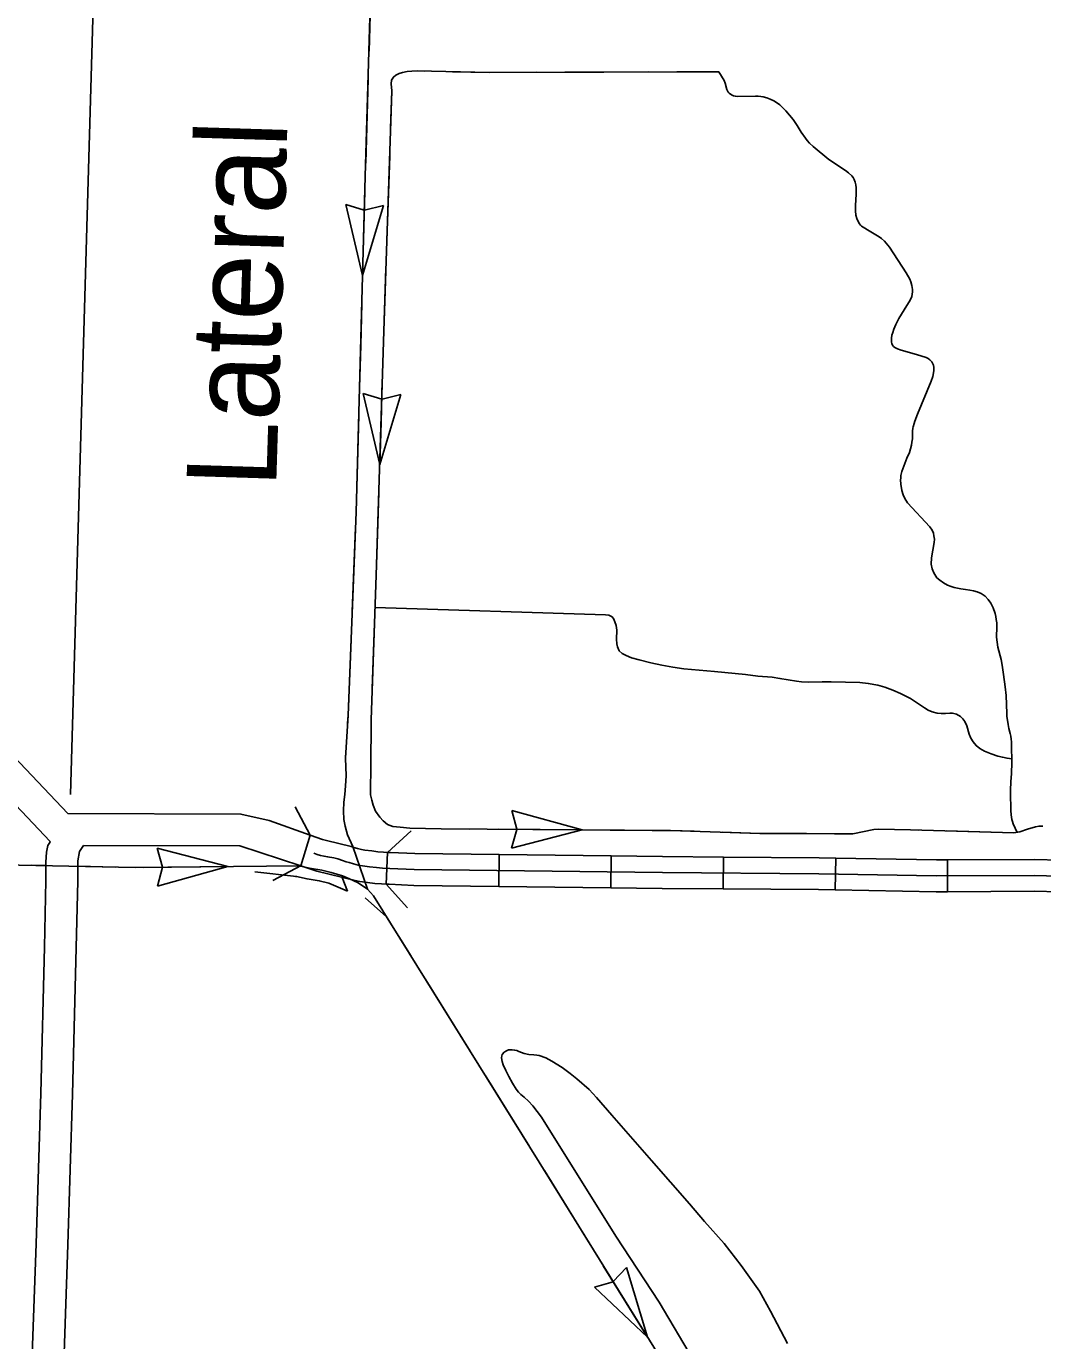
# Model space of a CAD drawing. Extents: x 1196286 to 1268366, y 2040822 to 2082115.
# Drawn here: x 1218140 to 1219934, y 2061099 to 2063420 of the extents above; entities that cross this region are included whole.
import ezdxf

# ---------------------------------------------------------------- set-up
doc = ezdxf.new("R2010")
doc.units = 0
for name, color, linetype in [('60', 7, 'Continuous'), ('61', 7, 'Continuous'), ('62', 7, 'Continuous'), ('63', 7, 'Continuous'), ('Level 72', 7, 'Continuous'), ('Level 83', 7, 'Continuous')]:
    doc.layers.add(name, color=color, linetype=linetype)

msp = doc.modelspace()

# ---------------------------------------------------------------- linework, layer by layer
at = {"layer": '60'}
msp.add_lwpolyline([(1218272.3, 2063944.2), (1218218.5, 2062063.5)], dxfattribs=at)
at = {"layer": '61'}
for p, q in [((1218777.8, 2061961.3), (1218775.3, 2061905.1)), ((1218974.8, 2061957.4), (1218974.2, 2061901.2)), ((1219172.8, 2061955), (1219172.1, 2061898.8)), ((1219370.7, 2061953), (1219370.2, 2061896.8)), ((1219569, 2061951.1), (1219567.9, 2061894.9)), ((1219766.3, 2061948), (1219766.6, 2061891.7))]:
    msp.add_line(p, q, dxfattribs=at)
for points in [[(1218775.3, 2061905.1), (1218767.4, 2061905.5), (1218755.5, 2061906.4), (1218742.6, 2061907.9), (1218729.1, 2061909.9), (1218720.6, 2061911.4), (1218653.1, 2061928.2), (1218644.2, 2061930.8), (1218625, 2061937.2), (1218641.6, 2061991.8)], [(1218777.8, 2061961.3), (1218770.7, 2061961.6), (1218761, 2061962.4), (1218749.9, 2061963.7), (1218738, 2061965.4), (1218731.8, 2061966.5), (1218724.8, 2061968.1), (1218718.4, 2061970), (1218713.9, 2061971.4), (1218670.3, 2061982.2), (1218663.2, 2061983.9), (1218641.4, 2061991.8)], [(1220136.9, 2061914.8), (1219919.4, 2061920.7), (1219746.6, 2061919.8), (1219539.2, 2061923.5), (1219263.2, 2061925.8), (1218825.1, 2061931.2), (1218781.8, 2061933), (1218769.1, 2061933.6), (1218758.3, 2061934.4), (1218746.2, 2061935.8), (1218733.5, 2061937.6), (1218726.2, 2061938.9), (1218717.7, 2061940.9), (1218710.2, 2061943.1), (1218704.9, 2061944.7), (1218698.2, 2061947.1), (1218690.1, 2061949.7), (1218682.9, 2061951.5), (1218672.2, 2061953.6), (1218665.9, 2061954.5), (1218659.6, 2061955.6), (1218653.7, 2061957.3), (1218648.1, 2061959.7)], [(1218974.8, 2061957.4), (1218825.8, 2061959.3), (1218783, 2061961.1), (1218777.8, 2061961.3)], [(1219172.8, 2061955), (1218974.8, 2061957.4)], [(1219370.7, 2061953), (1219263.5, 2061953.9), (1219172.8, 2061955)], [(1219569, 2061951.1), (1219539.6, 2061951.7), (1219370.7, 2061953)], [(1219766.3, 2061948), (1219746.8, 2061947.9), (1219569, 2061951.1)], [(1219965.2, 2061947.6), (1219919.7, 2061948.8), (1219766.3, 2061948)], [(1218974.2, 2061901.2), (1218824.3, 2061903), (1218780.6, 2061904.9), (1218775.3, 2061905.1)], [(1219172.1, 2061898.8), (1218974.2, 2061901.2)], [(1219370.2, 2061896.8), (1219262.9, 2061897.7), (1219172.1, 2061898.8)], [(1219567.9, 2061894.9), (1219538.9, 2061895.4), (1219370.2, 2061896.8)], [(1219766.6, 2061891.7), (1219746.4, 2061891.6), (1219567.9, 2061894.9)], [(1219963.7, 2061891.3), (1219919.1, 2061892.5), (1219766.6, 2061891.7)]]:
    msp.add_lwpolyline(points, dxfattribs=at)
at = {"layer": '62'}
for points in [[(1219362.9, 2063339.5), (1219372.3, 2063324), (1219374.1, 2063319.2), (1219376.6, 2063308.2), (1219377.7, 2063306), (1219379, 2063303.4), (1219380.8, 2063301.6), (1219383, 2063299.9), (1219386, 2063298.3), (1219388.8, 2063297.1), (1219391.9, 2063296.3), (1219395.6, 2063295.7), (1219427.6, 2063296.7), (1219432.3, 2063296.4), (1219437, 2063295.8), (1219441, 2063295.1), (1219447.3, 2063293.3), (1219453.3, 2063291), (1219459.7, 2063288.1), (1219464.3, 2063285.5), (1219470.5, 2063281.3), (1219480.9, 2063270.8), (1219493.8, 2063255.4), (1219501.2, 2063244.5), (1219508.3, 2063232.9), (1219515.4, 2063222.1), (1219518.4, 2063218.2), (1219522.5, 2063213.4), (1219529.3, 2063207.5), (1219557.1, 2063184.7), (1219565.2, 2063179.1), (1219576.5, 2063171.9), (1219586.5, 2063165.4), (1219591.7, 2063161.3), (1219597.3, 2063155.9), (1219599.7, 2063152.7), (1219601.6, 2063149.1), (1219603.3, 2063144.4), (1219604.4, 2063139.6), (1219605, 2063134.7), (1219605, 2063123.6), (1219604.1, 2063103.4), (1219604.2, 2063093.8), (1219604.8, 2063086.1), (1219606, 2063080.6), (1219608.4, 2063074.9), (1219610.8, 2063071.1), (1219612.8, 2063068.8), (1219614.8, 2063067.1), (1219630.9, 2063057.1), (1219645.5, 2063048.3), (1219649.7, 2063045.1), (1219655.4, 2063040.3), (1219663.8, 2063029.9), (1219693.1, 2062984.4), (1219699.7, 2062973.2), (1219701.6, 2062968.4), (1219703.4, 2062961.9), (1219704.5, 2062955.3), (1219704.6, 2062951.2), (1219704.2, 2062946.8), (1219703.2, 2062942.8), (1219700.6, 2062936.4), (1219689.9, 2062919.1), (1219680.6, 2062903.7), (1219675.3, 2062893.2), (1219671.6, 2062885.2), (1219669.6, 2062879.4), (1219668.2, 2062874.2), (1219667.4, 2062869.3), (1219667.3, 2062865.6), (1219667.3, 2062862.3), (1219667.9, 2062859.5), (1219669.2, 2062856.8), (1219671.1, 2062854.7), (1219673.5, 2062852.7), (1219678.3, 2062850.4), (1219684.7, 2062848.1), (1219707.3, 2062841.3), (1219719.4, 2062838), (1219728.9, 2062835.1), (1219732.3, 2062833.3), (1219735, 2062831), (1219738.4, 2062827.3), (1219740.2, 2062824.1), (1219741.5, 2062821.2), (1219742.1, 2062817.6), (1219742.2, 2062812.3), (1219741.7, 2062808), (1219740.3, 2062801.3), (1219737.6, 2062793.3), (1219713.5, 2062734.8), (1219708.8, 2062722.7), (1219707.2, 2062718.2), (1219705.9, 2062712.8), (1219705.3, 2062710.3), (1219704.8, 2062704.8)], [(1219704.8, 2062704.8), (1219704.7, 2062697.8), (1219704.4, 2062691.4), (1219703.6, 2062685.7), (1219702.7, 2062680.2), (1219701.2, 2062673.9), (1219699, 2062667.4), (1219694.7, 2062657.2), (1219689.1, 2062643.4), (1219685.8, 2062633.8), (1219684.1, 2062626.8), (1219683.7, 2062622.1), (1219683.4, 2062619.1), (1219683.7, 2062611.3), (1219685.6, 2062600.2), (1219688, 2062592.3), (1219690.8, 2062586), (1219695.5, 2062578.2), (1219735.4, 2062536.1), (1219739.4, 2062529.9), (1219741.4, 2062524.9), (1219742.4, 2062520), (1219743.3, 2062514.1), (1219742.8, 2062508.3), (1219738.1, 2062481.2), (1219737.7, 2062470), (1219739, 2062462.1), (1219741.9, 2062454.7), (1219747.3, 2062446), (1219752.6, 2062441.8), (1219759.1, 2062437.2), (1219766.1, 2062433.1), (1219772.5, 2062430.7), (1219778, 2062429.2), (1219790, 2062426.3), (1219798, 2062425.1), (1219805.5, 2062424.5), (1219812.3, 2062423.3), (1219818.8, 2062421.2), (1219826, 2062418.2), (1219832.8, 2062413.6), (1219837.9, 2062408), (1219842.8, 2062401), (1219847, 2062393.3), (1219850.6, 2062382.9), (1219851.9, 2062377.8), (1219852.5, 2062372.2), (1219853.3, 2062366.4), (1219853.6, 2062359.4), (1219853.1, 2062341.3), (1219853.7, 2062332.3), (1219855.3, 2062323.4), (1219860.9, 2062301.6), (1219862.6, 2062291.7), (1219865.4, 2062275.6), (1219868.3, 2062253.8), (1219869.8, 2062238.3), (1219871.1, 2062206.6), (1219871.3, 2062201.3), (1219872.1, 2062194.5), (1219873.5, 2062187.1), (1219874.8, 2062180.1), (1219877.1, 2062171.3), (1219878.2, 2062166.2), (1219878.7, 2062161.3), (1219879.1, 2062156.2), (1219879.2, 2062150.7), (1219879.8, 2062120), (1219879.2, 2062100.4), (1219878.3, 2062085.8), (1219877.7, 2062071.3), (1219877.6, 2062058.3), (1219878.1, 2062043.9), (1219878.3, 2062035.1), (1219878.7, 2062027.6), (1219879.7, 2062019.2), (1219880.8, 2062015.5), (1219882.1, 2062011.8), (1219889.3, 2061996.3)], [(1218756.1, 2062393.4), (1219162.9, 2062380.6), (1219168.7, 2062380.1), (1219174.2, 2062377.3), (1219177.2, 2062372.9), (1219181.6, 2062361.8), (1219182.5, 2062353.4), (1219181.9, 2062337.7), (1219182.6, 2062329.3), (1219183.9, 2062323.9), (1219186.9, 2062317.3), (1219192, 2062312.2), (1219199.3, 2062308.7), (1219208.5, 2062304.9), (1219221.8, 2062301.1), (1219242.8, 2062295.9), (1219262.3, 2062291.9), (1219281.6, 2062288.1), (1219301.2, 2062285.2), (1219341.4, 2062281.9), (1219355.1, 2062280.7), (1219409.7, 2062275.1), (1219431.8, 2062272.1), (1219456.8, 2062270.4), (1219470.5, 2062268.5), (1219500, 2062263.4), (1219508.9, 2062262.2), (1219520.5, 2062261.8), (1219545.3, 2062262.4), (1219560.7, 2062262.2), (1219611.5, 2062260.9), (1219626.5, 2062259.6), (1219643.3, 2062256.5), (1219655.6, 2062252.8), (1219670.1, 2062247.4), (1219683.2, 2062241.8), (1219701.1, 2062233), (1219725.8, 2062216.5), (1219732.2, 2062212.6), (1219739.5, 2062209.4), (1219748, 2062207), (1219755.2, 2062206.5), (1219763, 2062206.4), (1219770.5, 2062207), (1219775.2, 2062206.8), (1219782.2, 2062205.2), (1219789.5, 2062201), (1219793.3, 2062197.2), (1219796.7, 2062192.5), (1219800.2, 2062184.5), (1219804.5, 2062169.9), (1219807.7, 2062163), (1219811.4, 2062156.3), (1219816.7, 2062149.8), (1219823.1, 2062144.4), (1219831.6, 2062139.7), (1219843.2, 2062135.3), (1219855.4, 2062131.2), (1219863.2, 2062129.2), (1219871.6, 2062127.5), (1219879.7, 2062126.4)], [(1219483.9, 2061093.8), (1219454.1, 2061151.4), (1219434.2, 2061186.3), (1219402.1, 2061231.8), (1219372.3, 2061270.4), (1219337.4, 2061309.7), (1219311, 2061340.7), (1219243.8, 2061417.1), (1219174.1, 2061497.4), (1219146.5, 2061528.4), (1219133.7, 2061542.8), (1219112.2, 2061561.4), (1219100.4, 2061570.7), (1219086.2, 2061581.4), (1219067.8, 2061592.7), (1219057.1, 2061598.2), (1219045.5, 2061602.5), (1219041.4, 2061603.3), (1219036.1, 2061603.5), (1219027.6, 2061604.1), (1219019.2, 2061606.1), (1219009.7, 2061609.9), (1219006, 2061611.3), (1219002.1, 2061612.2), (1218997.9, 2061612.8), (1218991.4, 2061612.3), (1218988.1, 2061611), (1218984, 2061608.6), (1218980.2, 2061604.2), (1218979.4, 2061602), (1218979.1, 2061598.4), (1218980.2, 2061592.1), (1218982.3, 2061586.3), (1218986.8, 2061576.2), (1218992.2, 2061565.3), (1218998.3, 2061553.8), (1219004.9, 2061543), (1219008.8, 2061538.1), (1219013.2, 2061533.7), (1219019.1, 2061528.8), (1219027, 2061521.8), (1219034.2, 2061513.9), (1219049.7, 2061493.5), (1219180.9, 2061283.7), (1219257.6, 2061167.1), (1219378.4, 2060962.2)]]:
    msp.add_lwpolyline(points, dxfattribs=at)
at = {"layer": '63'}
for p, q in [((1218734, 2062980), (1218704.1, 2063105.2)), ((1218704.1, 2063105.2), (1218736.9, 2063095.4)), ((1218734, 2062980), (1218770.7, 2063103.4)), ((1218770.7, 2063103.4), (1218737.4, 2063095.4)), ((1218764.1, 2062646.3), (1218735, 2062771.6)), ((1218735, 2062771.6), (1218767.8, 2062761.7)), ((1218764.1, 2062646.3), (1218801.6, 2062769.4)), ((1218801.6, 2062769.4), (1218768.2, 2062761.7)), ((1219121.4, 2062000.9), (1218997.3, 2062035.1)), ((1218997.3, 2062035.1), (1219005.9, 2062002)), ((1218996.8, 2061968.5), (1219005.9, 2062001.5)), ((1219121.4, 2062000.9), (1218996.8, 2061968.5)), ((1218495.9, 2061936.2), (1218371.3, 2061968.4)), ((1218371.3, 2061968.4), (1218380.5, 2061935.4)), ((1218495.9, 2061936.2), (1218371.9, 2061901.7)), ((1218371.9, 2061901.7), (1218380.5, 2061934.9)), ((1218707.1, 2061892.5), (1218698, 2061917)), ((1219199.8, 2061228.3), (1219176.4, 2061203.4)), ((1219236.9, 2061105.1), (1219199.8, 2061228.3)), ((1219143.2, 2061193.3), (1219176, 2061203.1)), ((1219236.9, 2061105.1), (1219143.2, 2061193.3))]:
    msp.add_line(p, q, dxfattribs=at)
for points in [[(1218756.3, 2063757.3), (1218738.7, 2063154.7), (1218722.6, 2062561.9), (1218708.3, 2062203.4), (1218703.7, 2062127.3), (1218704.6, 2062096.3), (1218703.8, 2062078.6), (1218702.7, 2062063.7), (1218701, 2062049.9), (1218700.3, 2062034.5), (1218700.8, 2062019.4), (1218703, 2062007.3), (1218707.3, 2061992.1), (1218716.4, 2061971.8), (1218723.3, 2061952.7), (1218742.7, 2061896.2)], [(1218749.5, 2063524.3), (1218745.2, 2063375.9)], [(1219362.9, 2063339.5), (1218957.4, 2063338.4), (1218830, 2063340.9), (1218821, 2063340.6), (1218812.7, 2063339.8), (1218804.5, 2063338.5), (1218798.5, 2063336.6), (1218792.5, 2063333.7), (1218788.2, 2063330), (1218785, 2063324.8), (1218784.3, 2063318.3), (1218785.6, 2063305.8), (1218771.4, 2062881.7), (1218758.1, 2062450.7), (1218749.1, 2062195)], [(1218843.1, 2063340.6), (1218830, 2063340.9), (1218821, 2063340.6), (1218812.7, 2063339.8), (1218804.5, 2063338.5), (1218798.5, 2063336.6), (1218792.5, 2063333.7), (1218788.2, 2063330), (1218785, 2063324.8), (1218784.3, 2063318.3), (1218785.6, 2063305.8), (1218783.4, 2063240)], [(1219041.1, 2063338.7), (1218957.4, 2063338.4), (1218892.6, 2063339.7)], [(1219239.1, 2063339.2), (1219090.6, 2063338.8)], [(1219362.9, 2063339.5), (1219288.6, 2063339.3)], [(1218743.8, 2063326.4), (1218739.4, 2063178)], [(1218781.7, 2063190.5), (1218776.8, 2063042.1)], [(1218738, 2063128.5), (1218734, 2062980)], [(1218775.1, 2062992.6), (1218771.4, 2062881.7), (1218770.3, 2062844.2)], [(1218732.7, 2062930.6), (1218730.6, 2062856.3)], [(1218730.6, 2062856.3), (1218728.6, 2062782.1)], [(1218768.7, 2062794.7), (1218766.4, 2062720.5)], [(1218727.3, 2062732.6), (1218723.2, 2062584.2)], [(1218766.4, 2062720.5), (1218764.1, 2062646.3)], [(1218762.6, 2062596.8), (1218758.1, 2062450.7), (1218758, 2062448.4)], [(1218721.5, 2062534.7), (1218715.6, 2062386.3)], [(1218756.3, 2062398.9), (1218751, 2062250.5)], [(1218713.6, 2062336.9), (1218708.3, 2062203.4), (1218707.4, 2062188.5)], [(1218749.3, 2062201), (1218749.1, 2062195), (1218748.5, 2062109.8), (1218747.6, 2062072.4), (1218748.1, 2062062.8), (1218749.9, 2062053.6), (1218750.1, 2062052.8)], [(1218749.1, 2062195), (1218748.5, 2062109.8), (1218747.6, 2062072.4), (1218748.1, 2062062.8), (1218749.9, 2062053.6), (1218752.8, 2062044.6), (1218756.9, 2062034.1), (1218764.1, 2062023.4), (1218769.9, 2062017.1), (1218777.8, 2062010.7), (1218787.1, 2062006.9), (1218800.1, 2062005.5), (1218817.4, 2062003.8), (1218872.4, 2062002.7), (1219277.5, 2061999.8), (1219435.1, 2061994.6), (1219599.5, 2061994.1), (1219636.4, 2062001.4), (1219644.6, 2062002.5), (1219701, 2062000.8), (1219883.4, 2061995.9), (1219893.8, 2061997.4), (1219907.8, 2062002), (1219921.4, 2062006.2), (1219928.1, 2062007.8), (1219934.7, 2062007.5)], [(1218704.4, 2062139.1), (1218703.7, 2062127.3), (1218704.6, 2062096.3), (1218703.8, 2062078.6), (1218702.7, 2062063.7), (1218701, 2062049.9), (1218700.3, 2062034.5), (1218700.8, 2062019.4), (1218703, 2062007.3), (1218707.3, 2061992.1), (1218707.5, 2061991.7)], [(1218776.3, 2062012), (1218777.8, 2062010.7), (1218787.1, 2062006.9), (1218800.1, 2062005.5), (1218817.4, 2062003.8), (1218872.4, 2062002.7), (1218923.4, 2062002.3)], [(1218972.9, 2062002), (1219121.4, 2062000.9)], [(1219170.9, 2062000.6), (1219245.1, 2062000.1)], [(1219245.1, 2062000.1), (1219277.5, 2061999.8), (1219319.4, 2061998.4)], [(1219368.8, 2061996.8), (1219435.1, 2061994.6), (1219517.3, 2061994.3)], [(1219566.8, 2061994.2), (1219599.5, 2061994.1), (1219636.4, 2062001.4), (1219644.6, 2062002.5), (1219701, 2062000.8), (1219714.5, 2062000.4)], [(1219764, 2061999.1), (1219883.4, 2061995.9), (1219893.8, 2061997.4), (1219907.8, 2062002), (1219911.4, 2062003.1)], [(1217951.8, 2061942.3), (1218332.6, 2061934.7), (1218621.7, 2061937.5), (1218640.4, 2061933.2), (1218661.7, 2061929.7), (1218678.7, 2061925.6), (1218698.2, 2061919.6), (1218710.9, 2061914.7), (1218726, 2061907.2), (1218742.7, 2061896.2), (1218753.4, 2061884.6), (1219045.7, 2061414.3), (1219328.3, 2060957.3), (1219625.3, 2060475.6), (1219881.1, 2060055.8), (1220003.6, 2059850.4), (1220011.7, 2059838.9), (1220019.2, 2059831.7), (1220028.2, 2059821.9), (1220038.1, 2059813.7), (1220064, 2059796.3), (1220129.8, 2059748.8), (1220290.4, 2059650.9), (1220799.5, 2059331.1)], [(1218149.5, 2061938.4), (1218174.9, 2061937.8)], [(1218231.2, 2061936.7), (1218297.9, 2061935.4)], [(1218347.4, 2061934.8), (1218495.9, 2061936.2)], [(1218543.5, 2061926.7), (1218617.3, 2061918.7)], [(1218615.3, 2061918.7), (1218617.3, 2061918.7), (1218636, 2061914.5), (1218657.3, 2061911), (1218674.3, 2061906.8), (1218707.1, 2061892.5)], [(1218738.2, 2061881), (1218776.3, 2061847.7), (1218819.5, 2061778.2)], [(1218845.6, 2061736.1), (1218924, 2061610)], [(1218950.2, 2061568), (1219028.6, 2061441.8)], [(1219054.7, 2061399.8), (1219132.8, 2061273.5)], [(1219158.8, 2061231.4), (1219236.9, 2061105.1)]]:
    msp.add_lwpolyline(points, dxfattribs=at)
at = {"layer": 'Level 72'}
for points in [[(1218213.4, 2062029.9), (1217979.5, 2062276.4), (1217733.7, 2062536.2), (1217486.9, 2062795.5), (1217149.4, 2063150.4), (1216929.9, 2063381), (1216738.6, 2063580), (1216482.4, 2063845.8), (1216344.7, 2063988.4), (1216333.8, 2063997.2), (1216319.9, 2064001.4), (1216305.1, 2064002.8), (1216223, 2064001.9), (1216116.5, 2064003.2), (1215787.6, 2064012.1)], [(1218136.9, 2060745.6), (1218148.3, 2061010), (1218157.6, 2061270.2), (1218165.7, 2061536), (1218172.2, 2061794.1), (1218174.9, 2061911.5), (1218174.9, 2061944), (1218175.7, 2061961.5), (1218178.3, 2061973.2), (1218182, 2061978.4), (1218182.6, 2061980.6), (1217938.7, 2062237.7)], [(1218641.6, 2061991.8), (1218569.2, 2062017.5), (1218519.1, 2062028.9), (1218213.4, 2062029.9)], [(1218204.5, 2061007.8), (1218213.8, 2061268.3), (1218222, 2061534.4), (1218228.4, 2061792.7), (1218231.2, 2061910.9), (1218231.2, 2061942.8), (1218231.3, 2061946.5), (1218234.2, 2061962.5), (1218241.2, 2061973.5)], [(1218625, 2061937.2), (1218517.4, 2061972.6), (1218241.2, 2061973.5)]]:
    msp.add_lwpolyline(points, dxfattribs=at)
at = {"layer": 'Level 83'}
for points in [[(1218615.1, 2062041.4), (1218641.6, 2061991.8)], [(1218777.8, 2061961.3), (1218819.4, 2061999.3)], [(1218625.2, 2061937.9), (1218575.6, 2061911.5)], [(1218813.2, 2061863.6), (1218775.3, 2061905.1)]]:
    msp.add_lwpolyline(points, dxfattribs=at)

# ---------------------------------------------------------------- texts
at = {"layer": '63'}
msp.add_text('Lateral', height=158.4, rotation=88.2181, dxfattribs=at).set_placement((1218581.2, 2062603.6))

doc.saveas('drawing.dxf')
